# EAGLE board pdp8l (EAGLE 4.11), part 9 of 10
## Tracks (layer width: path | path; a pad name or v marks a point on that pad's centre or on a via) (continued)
OP1  (via drill 0.61) (continued)
  Bottom 0.203: v343,97.38 343.41,96.98 v365.76,96.98 | A09.D1 350.32,263.2 348.69,261.57 344.22,261.57 341.38,258.72 327.15,258.72 325.93,257.5 A11.F1 324.71,257.1 323.09,255.47 317.81,255.47 316.59,254.25 A12.H1 | B13.H2 297.49,183.95 302.77,183.95 B13.H1 | v316.59,205.08 v304.8,205.08
OP1\  (via drill 0.61)
  Route2 0.203: v300.74,146.96 299.52,145.75 299.52,144.93 v294.23,139.65 291.8,137.21 290.98,137.21 C14.A1
  Route15 0.203: v300.74,146.96 301.95,148.18 306.43,143.71 306.43,142.49 319.43,129.49 319.43,128.68 330,118.11 330,116.08 331.22,114.86 C10.J2 | v367.79,125.02 361.29,131.52 356.01,131.52 353.16,134.37 351.94,134.37 348.29,138.02 346.66,138.02 v345.44,139.24
  Bottom 0.203: v367.79,125.02 371.04,125.02 372.26,123.8 C07.E2 | v345.44,139.24 345.03,138.84 339.34,138.84 338.94,139.24 338.94,140.06 313.33,140.06 312.12,138.84 305.61,138.84 304.39,140.06 294.64,140.06 v294.23,139.65
OP2  (via drill 0.61)
  Top 0.203: v345.85,57.96 345.85,52.68 344.63,51.46 D09.F2 | v311.3,126.24 v311.3,115.27 | v302.36,139.24 302.77,139.65 302.77,147.37 301.55,148.59 301.55,200.61 301.14,201.02 301.14,206.3 301.55,206.7 301.55,220.52 298.3,223.77 298.3,233.12 297.08,234.34 A13.P2 | v354.79,70.97 355.19,70.56 355.19,61.62 354.38,60.81 D09.C1 | v365.35,78.69 362.1,81.94 362.1,83.16 363.32,84.38 368.61,84.38 368.61,109.98 369.82,111.2 369.82,113.64 C07.J2
  Route15 0.203: v302.36,139.24 302.36,138.02 301.14,136.8 302.77,135.18 306.83,135.18 308.05,133.96 308.05,133.55 310.9,130.71 310.9,127.05 311.3,126.64 v311.3,126.24
  Bottom 0.203: v345.85,57.96 347.07,59.18 349.91,59.18 350.72,60 353.57,60 D09.C1 | 311.3,115.67 345.85,115.67 346.25,115.27 349.91,115.27 350.32,115.67 368.61,115.67 369.42,114.86 C07.J2 | 311.3,115.67 286.51,115.67 285.29,114.45 281.63,114.45 C14.J2 | v311.3,126.24 307.24,126.24 306.83,126.64 C12.D2 | v311.3,115.27 311.3,115.67 | v354.79,70.97 354.79,77.88 360.48,77.88 361.7,79.1 364.95,79.1 v365.35,78.69
OP2\  (via drill 0.61)
  Route2 0.203: v351.94,100.23 351.94,100.63 363.73,112.42 364.13,112.42 370.23,118.52 371.04,117.7 372.26,117.7 C07.H2
  Route15 0.203: C14.B1 288.14,133.15 289.36,133.15 293.83,128.68 294.64,128.68 296.27,127.05 297.89,127.05 308.86,116.08 314.15,116.08 321.87,108.36 323.09,108.36 331.22,100.23 333.25,100.23 334.47,99.01 C10.P2
  Bottom 0.203: v351.94,100.23 337.31,100.23 335.69,98.6 C10.P2
OP_STROBE\  (via drill 0.61)
  Top 0.203: v319.43,222.15 319.43,224.99 A11.T2 | v362.92,178.66 361.7,177.44 361.7,154.28 360.48,153.06 B08.U2
  Route2 0.203: v322.27,156.31 322.27,155.91 315.77,149.4 314.96,149.4 310.9,145.34 310.9,144.93 303.99,138.02 302.77,138.02 295.05,130.3 295.05,126.24 289.76,120.95 288.14,120.95 C14.F1
  Route15 0.203: v322.27,156.31 322.68,156.31 v325.12,153.87 | v319.43,222.15 348.29,193.29 348.29,192.89 354.38,186.79 354.79,186.79 v362.92,178.66
  Bottom 0.203: v325.12,153.87 327.96,151.03 333.25,151.03 334.47,149.81 335.28,149.81 338.12,152.65 338.94,152.65 340.56,151.03 355.6,151.03 356.82,152.25 359.66,152.25 B08.U2
OUT_STOP2\
  Bottom 0.203: D31.N2 65.84,31.55 70.71,31.55 D31.N1
PANEL_LOCK  (via drill 0.61)
  Route2 0.203: v382.83,103.48 382.83,103.89 384.86,105.92 386.89,105.92 387.71,106.73 387.71,108.76 426.72,147.78 427.53,147.78 445.82,166.06 445.82,167.69 B01.N2 | v377.55,103.48 375.92,103.48 364.54,92.1 v364.54,91.69 | v323.09,90.47 322.68,90.47 313.33,81.13 309.68,81.13 299.11,70.56 298.3,70.56 297.89,70.16 278.38,70.16 v260.1,51.87
  Route15 0.203: v260.1,51.87 258.06,51.87 247.5,62.43 245.87,62.43 170.28,138.02 167.44,138.02 136.14,169.32 136.14,175.41 128.42,183.13 128.42,185.57 107.29,206.7 107.29,207.11 105.26,209.14 105.26,219.71 102.82,222.15 102.82,224.99 A28A.T2
  Bottom 0.203: v377.55,103.48 v382.83,103.48 | v364.54,91.69 363.73,90.88 359.26,90.88 357.63,92.51 356.41,92.51 354.79,90.88 350.72,90.88 348.29,93.32 326.75,93.32 323.9,90.47 v323.09,90.47
PAUSE  (via drill 0.61)
  Top 0.203: v416.15,101.04 416.15,105.51 414.53,107.14 C04.L1
  Route2 0.203: v430.38,77.47 430.38,77.06 426.31,73 426.31,72.19 391.36,37.24 390.14,37.24 364.13,11.23 352.75,11.23 352.35,10.82 349.5,10.82 v343.41,4.72
  Route15 0.203: v416.15,101.04 416.15,95.35 428.35,83.16 428.35,79.5 v430.38,77.47 | v343.41,4.72 324.31,4.72 321.06,1.47 300.33,1.47 297.49,4.32 294.23,4.32 287.73,10.82 286.51,10.82 272.69,24.64 271.07,24.64 269.04,26.67 258.88,26.67 258.06,27.48 255.63,27.48 253.19,29.92 241.4,29.92 234.49,36.83 227.99,36.83 209.3,55.52 204.01,55.52 191.82,67.72 191.01,67.72 v126.39,132.33
  Bottom 0.203: v126.39,132.33 123.55,135.18 114.61,135.18 113.39,136.4 C28.A1
PAUSE\  (via drill 0.61)
  Top 0.203: v421.44,65.28 421.84,65.68 v421.84,103.89
  Bottom 0.203: v421.44,65.28 420.62,65.28 419.81,64.47 415.34,64.47 414.93,64.06 D04.B1 | v421.84,103.89 421.44,104.29 418.19,104.29 C04.M1
PC_ENABLE  (via drill 0.61)
  Top 0.203: v357.23,205.08 357.23,218.49 A08.V2 | v373.48,185.98 374.29,185.17 374.29,160.78 373.07,159.56 AB07.BS2
  Route15 0.203: v357.23,205.08 357.23,202.23 v373.48,185.98
  Bottom 0.203: AB07.BS2 373.48,159.16 374.29,159.97 384.45,159.97 385.27,159.16 AB06.BS2 386.49,159.16 387.3,159.97 397.05,159.97 | 397.05,159.97 397.87,159.16 AB05.BS2 | 409.65,159.97 410.46,159.16 AB04.BS2 | 397.05,159.97 409.65,159.97 | 421.84,159.97 423.06,158.75 AB03.BS2 | 409.65,159.97 421.84,159.97 | 421.84,159.97 435.25,159.97 436.07,159.16 AB02.BS2
PC_ENABLE\  (via drill 0.61)
  Top 0.203: v296.67,112.83 295.05,114.45 295.05,144.53 294.64,144.93 294.64,148.18 295.05,148.59 295.05,175.82 295.45,176.22 v295.45,186.79 295.45,187.2 295.45,203.45 v293.01,205.89
  Route2 0.203: v341.78,212.8 354.38,225.4 356.41,225.4 A08.T2 | v332.44,212.39 329.59,209.55 326.75,209.55 305.61,188.42 v303.58,188.42
  Route15 0.203: v293.01,205.89 284.48,214.43 284.48,215.24 281.23,218.49 A14.V2
  Bottom 0.203: v296.67,112.83 301.55,112.83 302.77,111.61 C13.K1 | v295.45,186.79 299.52,186.79 B13.F1 300.74,187.6 302.77,187.6 v303.58,188.42 | v341.78,212.8 341.38,212.39 v332.44,212.39
PC_LOAD  (via drill 0.61)
  Top 0.203: v358.44,235.56 358.44,231.09 358.04,230.68 358.04,227.43 358.44,227.03 358.44,218.08 358.04,217.68 358.04,203.45 358.44,203.05 358.44,186.79 358.04,186.38 358.04,181.91 357.63,181.51 B08.J2
  Route2 0.203: C14.H1 290.98,118.11 290.98,120.14 305.61,134.77 309.68,134.77 320.24,145.34 321.06,145.34 322.27,146.56 322.27,148.18 347.07,172.97 347.88,172.97 349.1,174.19 349.1,175.01 353.16,179.07 354.79,179.07 356.41,180.7 B08.J2
  Route15 0.203: C14.J1 288.14,114.45 290.58,116.89 C14.H1
  Bottom 0.203: v358.44,235.56 359.66,236.78 368.61,236.78 | 368.61,236.78 369.42,237.59 AB07.AN2 | 381.2,236.78 382.02,237.59 AB06.AN2 | 368.61,236.78 381.2,236.78 | 381.2,236.78 389.74,236.78 390.14,237.19 393.8,237.19 394.61,238 AB05.AN2 395.83,237.59 400.3,237.59 401.12,236.78 402.34,236.78 402.74,237.19 406.4,237.19 407.21,238 AB04.AN2 408.43,238 412.5,238 413.71,236.78 419.4,236.78 420.22,237.59 AB03.AN2 421.44,238 424.28,238 425.5,236.78 432,236.78 432.82,237.59 AB02.AN2
POWER_CLEAR\  (via drill 0.61)
  Top 0.203: v403.15,93.73 403.56,94.13 403.56,102.26 404.37,103.07 404.37,104.29 C05.M1 405.18,105.51 v405.18,106.73 | v262.13,42.11 263.35,43.33 263.35,64.87 264.57,66.09 D16.A1 | v119.48,206.3 120.29,207.11 120.29,226.62 119.08,227.84 A27.S2
  Route2 0.203: v262.13,42.11 261.72,41.71 259.28,41.71 D16.K2 | v372.67,94.13 371.45,94.13 365.35,88.04 365.35,86.41 351.54,72.59 351.54,72.19 349.91,70.56 349.1,70.56 348.69,70.16 347.88,70.16 325.12,47.4 324.31,47.4 v316.18,39.27
  Route15 0.203: v119.48,206.3 119.48,204.67 130.05,194.11 130.05,189.23 153.21,166.06 153.21,164.44 155.25,162.41 155.25,158.75 166.22,147.78 167.03,147.78 242.21,72.59 242.21,72.19 243.84,70.56 244.65,70.56 245.06,70.16 245.87,70.16 v248.31,67.72
  Bottom 0.203: v403.15,93.73 390.96,93.73 389.74,94.94 C06.R1 388.52,94.54 387.71,93.73 373.07,93.73 v372.67,94.13 | v405.18,106.73 419.4,106.73 420.22,107.54 CD03.AL2 | v248.31,67.72 248.72,68.12 261.31,68.12 262.53,66.9 264.57,66.9 D16.A1 | v316.18,39.27 315.77,39.68 264.16,39.68 262.13,41.71 v262.13,42.11
POWER_OK\  (via drill 0.61)
  Top 0.203: v114.61,229.87 114.61,249.38 115.42,250.19 A27.J2
  Route15 0.203: v114.61,229.87 115.01,229.87 151.59,193.29 151.59,192.48 168.25,175.82 168.25,175.01 193.45,149.81 193.45,146.96 218.64,121.77 220.68,121.77 251.56,90.88 263.75,90.88 289.36,65.28 293.83,65.28 322.27,36.83 323.09,36.83 v323.9,37.64
  Bottom 0.203: v323.9,37.64 324.71,36.83 349.5,36.83 350.32,37.64 D09.L1
PROTECT\  (via drill 0.61)
  Top 0.203: v356.41,234.34 356.82,234.75 356.82,237.59 A08.N2 | 320.24,106.32 320.24,90.47 319.43,89.66 C11.T2 319.43,88.44 319.84,88.04 319.84,83.97 321.46,82.35 321.46,79.91 321.87,79.5 v321.87,72.19 | 320.24,106.32 319.43,107.14 C11.L2 | 384.45,3.5 349.5,3.5 349.5,17.73 345.85,21.39 345.85,30.33 | 384.45,3.5 404.77,3.5 413.71,12.45 D04.V1 | 345.85,30.33 345.03,31.14 D09.N2 | 384.45,3.5 384.45,82.75 382.83,84.38 382.83,88.44 C06.T2 | v345.03,48.21 345.85,47.4 345.85,30.33 | v325.53,146.56 325.93,146.15 v325.93,136.4 | v318.62,128.68 320.24,128.68 320.24,106.32
  Route2 0.203: v356.41,234.34 322.68,200.61 321.46,200.61 321.06,200.2 321.06,199.8 308.05,186.79 308.05,185.98 299.52,177.44 299.52,177.04 297.08,174.6 297.08,172.16 B13.M2 | v325.93,136.4 325.93,135.99 v318.62,128.68
  Route15 0.203: C12.R1 312.93,94.54 312.93,92.91 314.96,90.88 316.99,90.88 318.62,89.26 C11.T2 | v321.87,72.19 325.12,68.94 325.12,68.12 v345.03,48.21 | v325.53,146.56 325.12,146.56 310.49,161.19 310.08,161.19 305.21,166.06 304.39,166.06 299.52,170.94 297.49,170.94 B13.M2
PWR  (via drill 0.61)
  Top 0.203: v65.02,90.47 66.24,91.69 66.24,115.27 63.4,118.11 63.4,142.09 v62.99,142.49
  Route2 0.203: v62.99,142.49 62.99,144.93 76,157.94 76,159.56 77.62,161.19 AB30.BR2
  Bottom 0.203: v65.02,90.47 58.12,90.47 55.27,87.63 32.51,87.63 30.89,86 C34.U2
PWR_LOW\  (via drill 0.61)
  Top 0.203: v99.16,96.98 95.1,101.04 95.1,112.01 92.25,114.86 92.25,138.02 95.5,141.28 95.5,163.22 96.32,164.03 v96.32,166.06
  Route15 0.203: v96.32,166.06 66.65,195.73 65.43,195.73 47.55,213.61 47.14,213.61 40.23,220.52 34.95,220.52 v23.16,232.31
  Bottom 0.203: 18.69,236.78 37.8,236.78 39.01,238 A33.N2 | 18.69,236.78 2.03,236.78 2.03,232.31 A36.R2 | v99.16,96.98 117.04,96.98 120.7,93.32 130.45,93.32 131.27,92.51 C26.S2 | v23.16,232.31 18.69,236.78
PWR_SKP\  (via drill 0.61)
  Top 0.203: v45.52,241.66 48.77,244.91 48.77,246.94 A33.K1
  Bottom 0.203: v45.52,241.66 43.89,240.03 17.07,240.03 14.63,242.47 3.66,242.47 2.03,244.09 A36.L2
RD_HOLE1  (via drill 0.61)
  Top 0.203: v12.19,144.12 11.79,144.53 11.79,149.81 9.75,151.84 v9.75,185.98
  Route2 0.203: v9.75,185.98 9.75,192.07 24.79,207.11 24.79,208.33 76,259.54 76,261.16 77.62,262.79 AB30.AD2
  Bottom 0.203: v12.19,144.12 3.25,144.12 3.25,129.49 4.06,128.68 25.2,128.68 26.42,127.46 C34.D2
RD_HOLE2  (via drill 0.61)
  Top 0.203: v83.72,240.84 85.34,242.47 85.34,260.76 84.53,261.57 84.53,262.79 AB30.AD1
  Route2 0.203: v4.06,146.15 5.69,147.78 5.69,150.22 8.13,152.65 8.13,153.87 9.35,155.09 9.35,159.97 40.23,190.86 40.64,190.86 41.05,191.26 41.05,198.98 47.95,205.89 47.95,206.7 56.49,215.24 57.3,215.24 57.71,215.65 58.52,215.65 v83.72,240.84
  Bottom 0.203: v4.06,146.15 2.85,146.15 2.85,129.08 3.66,128.27 21.54,128.27 25.2,124.61 29.26,124.61 29.67,124.21 C34.E2
RD_HOLE3  (via drill 0.61)
  Top 0.203: v82.91,206.3 82.91,227.84 85.75,230.68 85.75,264.01 84.94,264.82 81.28,264.82 81.28,261.16 AB30.AE2
  Route2 0.203: v82.91,206.3 82.09,205.49 82.09,202.23 69.9,190.04 69.9,182.73 69.49,182.32 69.49,177.04 62.18,169.72 62.18,167.28 50.39,155.5 50.39,151.44 49.99,151.03 49.99,148.59 37.8,136.4 37.8,135.59 27.23,125.02 27.23,121.36 C34.F2
RD_HOLE4  (via drill 0.61)
  Top 0.203: v102.41,201.42 98.75,201.42 98.75,227.84 95.5,231.09 95.5,250.19 87.38,258.32 87.38,259.54 AB30.AE1
  Route2 0.203: v52.02,129.08 52.02,129.9 57.3,135.18 57.3,137.21 57.71,137.62 57.71,138.43 61.77,142.49 61.77,148.18 80.06,166.47 80.06,167.69 82.5,170.13 82.5,177.44 88.59,183.54 88.59,187.6 v102.41,201.42
  Bottom 0.203: v52.02,129.08 51.61,128.68 38.61,128.68 32.51,122.58 13.01,122.58 13.01,119.74 16.66,116.08 18.29,116.08 21.13,118.92 28.85,118.92 29.67,118.11 C34.H2
RD_HOLE5  (via drill 0.61)
  Route2 0.203: v5.69,141.28 5.69,146.96 6.1,147.37 6.1,149.81 8.53,152.25 8.53,153.47 9.75,154.69 9.75,159.56 40.64,190.45 41.05,190.45 41.45,190.86 41.45,197.36 45.52,201.42 51.61,201.42 54.86,204.67 58.52,204.67 62.99,209.14 62.99,218.9 84.53,240.44 84.53,241.66 77.62,248.56 79.25,250.19 79.25,252.22 80.47,253.44 AB30.AH2
  Route15 0.203: v5.69,141.28 8.94,138.02 8.94,135.18 26.42,117.7 26.42,114.86 C34.J2
RD_HOLE6  (via drill 0.61)
  Route2 0.203: v4.06,115.67 1.22,118.52 2.85,120.14 2.85,133.96 4.06,135.18 5.28,135.18 6.1,135.99 6.1,136.8 13.01,143.71 13.01,145.75 15.44,148.18 15.44,153.06 19.1,156.72 19.1,157.53 39.01,177.44 39.01,178.26 41.05,180.29 41.05,184.35 45.52,188.82 45.52,190.45 63.4,208.33 63.4,215.24 85.34,237.19 85.34,251.82 86.97,253.44 AB30.AH1
  Bottom 0.203: v4.06,115.67 6.91,112.83 8.13,112.83 8.53,112.42 28.85,112.42 29.67,111.61 C34.K2
RD_HOLE7  (via drill 0.61)
  Top 0.203: v116.23,177.44 117.04,178.26 117.04,211.18 115.42,212.8 115.42,217.68 107.7,225.4 107.7,229.06 103.63,233.12 101.6,233.12 101.6,231.5 100.79,230.68 98.35,230.68 98.35,253.44 86.56,265.23 79.25,265.23 79.25,259.13 78.03,257.91 AB30.AF2
  Route2 0.203: v49.58,109.17 49.99,109.17 76.4,135.59 76.4,138.02 115.82,177.44 v116.23,177.44
  Bottom 0.203: v49.58,109.17 28.45,109.17 27.64,108.36 C34.L2
RD_HOLE8  (via drill 0.61)
  Top 0.203: v31.7,135.99 31.29,135.59 31.29,106.32 30.48,105.51 C34.M2 | v48.36,138.02 48.36,149.81 49.58,151.03 50.39,151.03 50.39,167.69 v48.77,169.32
  Route2 0.203: v57.71,169.72 58.12,169.72 62.18,173.79 62.59,173.79 63.8,175.01 63.8,175.41 68.28,179.88 68.68,179.88 69.09,180.29 69.09,182.73 69.49,183.13 69.49,196.14 101.19,227.84 101.19,242.06 85.34,257.91 84.94,257.5 AB30.AF1
  Bottom 0.203: v31.7,135.99 32.51,135.18 39.42,135.18 42.27,138.02 44.7,138.02 45.11,137.62 47.95,137.62 v48.36,138.02 | v48.77,169.32 49.17,169.72 v57.71,169.72
RDR_FEED_SW  (via drill 0.61)
  Top 0.203: v87.38,133.96 88.19,134.77 88.19,135.59 92.25,139.65 92.25,163.22 93.47,164.44 AB29.BP2
  Route2 0.203: v87.38,133.96 81.69,128.27 77.22,128.27 69.49,120.55 69.49,116.48 40.23,87.22 35.76,87.22 31.29,82.75 27.64,82.75 C34.V2
  Bottom 0.203: AB30.BM1 87.78,170.94 88.19,170.54 91.44,170.54 94.69,167.28 94.69,165.66 93.88,165.66 AB29.BP2
RDR_INT\  (via drill 0.61)
  Top 0.203: v80.47,180.29 81.28,181.1 81.28,182.32 82.09,183.13 82.09,248.56 81.69,248.97 78.44,248.97 78.44,244.91 AB30.AL2
  Route2 0.203: v80.47,180.29 69.49,169.32 69.49,164.44 68.28,163.22 68.28,159.56 AB31.BS2
  Bottom 0.203: A33.L2 40.23,244.09 41.05,243.28 76.4,243.28 77.22,244.09 AB30.AL2
RDR_SKP\  (via drill 0.61)
  Top 0.203: v77.22,170.13 79.25,172.16 79.25,220.12 78.84,220.52 78.84,224.59 79.65,225.4 79.65,245.72 80.87,246.94 AB30.AK2
  Bottom 0.203: A33.H1 49.99,253.85 51.21,252.63 84.53,252.63 85.34,251.82 85.34,248.16 81.28,248.16 AB30.AK2 | v77.22,170.13 67.46,170.13 65.84,168.5 AB31.BN2
READ  (via drill 0.61)
  Top 0.203: v250.34,40.08 248.31,42.11 248.31,43.33 247.9,43.74 247.9,66.09 250.34,68.53 250.34,79.5 244.25,85.6 244.25,93.32 243.03,94.54 C17.R2 | D25.L1 147.52,38.86 146.3,40.08 146.3,55.12 147.52,56.34 D25.D1 147.52,57.96 146.3,59.18 146.3,69.34 149.15,72.19 149.15,83.16 143.05,89.26 143.05,106.73 | 143.05,106.73 143.05,124.61 141.43,126.24 C25.D2 | 143.05,106.73 144.27,105.51 C25.M2
  Route2 0.203: C17.R2 242.21,94.94 238.15,94.94 227.58,84.38 191.82,84.38 149.56,42.11 149.56,40.49 147.93,38.86 D25.L1
  Bottom 0.203: v250.34,40.08 259.69,40.08 261.31,38.46 D16.L1
READER_RUN  (via drill 0.61)
  Top 0.203: v53.24,86.82 53.65,86.41 53.65,78.28 47.95,72.59 47.95,35.2 43.48,35.2 D33.M2
  Bottom 0.203: v53.24,86.82 54.05,86 54.86,86 C32.U2
RESTART\  (via drill 0.61)
  Top 0.203: 409.25,87.22 v407.62,87.22 | 409.25,87.22 409.25,93.32 v409.65,93.73 | v408.03,42.52 409.25,43.74 409.25,87.22 | v311.3,79.5 v311.3,111.2 | v11.79,218.49 11.79,221.34 11.38,221.74 A36.U1 | v134.11,198.58 133.71,198.17 133.71,92.1 136.14,89.66 136.14,86.41 135.74,86 132.49,86 C26.U2 | v392.99,73 392.99,77.06 393.39,77.47 393.39,87.22 394.61,88.44 C05.T2
  Route2 0.203: C02.B1 440.13,132.74 440.13,128.68 442.98,125.83 441.76,124.61 441.76,118.52 422.66,99.42 422.66,97.38 421.03,95.76 CD03.AR2 | v106.48,205.49 127.2,205.49 v134.11,198.58
  Route15 0.203: v408.03,42.52 412.09,38.46 413.71,38.46 D04.L1 | v371.04,70.56 368.2,67.72 367.79,68.12 345.44,68.12 v335.28,78.28
  Bottom 0.203: v407.62,87.22 407.21,87.63 401.12,87.63 400.71,88.04 396.24,88.04 395.83,88.44 C05.T2 | v409.65,93.73 417.78,93.73 419,94.94 420.22,94.94 CD03.AR2 | v311.3,111.2 315.37,111.2 C12.K1 | C26.U2 132.08,85.19 132.08,80.72 199.14,80.72 200.35,81.94 203.2,81.94 206.04,79.1 272.69,79.1 273.1,78.69 295.45,78.69 296.67,79.91 310.9,79.91 v311.3,79.5 311.71,79.5 313.33,79.5 314.15,78.69 314.96,78.69 316.59,77.06 334.06,77.06 v335.28,78.28 | v11.79,218.49 21.13,209.14 38.61,209.14 41.05,206.7 45.52,206.7 45.92,207.11 55.68,207.11 57.3,205.49 v106.48,205.49 | v392.99,73 391.36,71.37 371.86,71.37 v371.04,70.56
RIGHT_SHIFT  (via drill 0.61)
  Top 0.203: v350.32,192.07 350.72,191.67 350.72,189.64 352.75,187.6 352.75,175.41 355.19,172.97 355.19,160.78 353.97,159.56 B09.S1 | v373.07,214.43 374.7,216.05 374.7,264.01 378.76,268.07 382.02,268.07 382.02,264.01 AB06.AD2
  Route2 0.203: v373.07,214.43 366.17,207.52 365.76,207.52 361.7,203.45 361.7,202.64 351.13,192.07 350.72,192.07 v350.32,192.07
  Bottom 0.203: v350.32,192.07 349.1,192.07 348.29,192.89 347.47,192.89 347.07,192.48 340.16,192.48 338.94,193.7 B10.D1 | AB02.AD2 432.82,264.01 428.75,264.01 427.94,264.82 422.66,264.82 421.44,263.6 AB03.AD2 420.22,264.01 419.4,264.82 412.9,264.82 412.09,264.01 408.43,264.01 AB04.AD2 407.21,263.6 406.81,264.01 403.15,264.01 402.34,264.82 393.8,264.82 | 381.2,264.82 375.51,264.82 374.7,264.01 371.04,264.01 370.64,263.6 AB07.AD2 | 381.2,264.82 382.02,264.01 AB06.AD2 | 393.8,264.82 394.61,264.01 AB05.AD2 | 381.2,264.82 393.8,264.82
RUN  (via drill 0.61)
  Top 0.203: v396.65,68.12 392.18,72.59 392.18,85.19 C06.U1 | v416.15,68.12 416.15,64.87 416.97,64.06 416.97,60.81 D04.C1
  Bottom 0.203: v396.65,68.12 397.05,68.53 415.75,68.53 v416.15,68.12
RUN\  (via drill 0.61)
  Top 0.203: v422.66,90.88 422.66,96.98 423.47,97.79 CD03.AP2 | v320.65,19.36 326.75,13.26 326.75,10.82 336.5,10.82 v336.5,12.04
  Route2 0.203: v336.5,12.04 338.53,10.01 339.34,10.82 345.03,10.82 360.48,26.26 361.7,26.26 387.71,52.27 387.71,53.09 405.99,71.37 406.81,71.37 407.62,72.19 407.62,73.81 410.46,76.66 410.46,77.06 411.28,77.88 411.28,78.69 412.09,79.5 413.31,79.5 421.84,88.04 421.84,89.66 422.66,90.47 v422.66,90.88
  Route15 0.203: v222.3,22.2 222.3,22.61 118.26,126.64 116.64,126.64 C27.D2
  Bottom 0.203: v422.66,90.88 397.46,90.88 397.05,91.29 392.99,91.29 392.58,91.69 C06.S1 | v222.3,22.2 223.52,20.98 319.02,20.98 v320.65,19.36
RXD
  Top 0.203: D32.M2 54.86,34.8 50.39,34.8 50.39,33.98 49.99,33.58 41.45,33.58 41.45,52.68 42.27,53.49 D33.E2
SET_IO_ON\  (via drill 0.61)
  Top 0.203: v364.54,139.24 364.54,143.71 364.95,144.12 364.95,179.48 362.92,179.48 362.1,180.29 362.1,182.32 360.88,183.54 B08.H2 | v392.99,139.24 393.39,138.84 393.39,112.42 | 393.39,112.42 392.58,111.61 C06.K1 | v392.99,101.45 393.39,101.85 393.39,112.42
  Route2 0.203: v392.99,101.45 394.61,101.45 C05.N2
  Bottom 0.203: v364.54,139.24 364.95,139.65 392.58,139.65 v392.99,139.24
SHIFT  (via drill 0.61)
  Top 0.203: v86.16,223.37 85.75,222.96 85.75,182.73 84.53,181.51 AB30.BJ1
  Bottom 0.203: v86.16,223.37 89.81,227.03 91.85,227.03 93.07,228.24 AB29.AS2
SHIFT\
  Top 0.203: AB30.BD1 84.53,194.11 85.34,194.92 85.34,225.4 85.75,225.81 89.81,225.81 AB29.AT2
SHUT_DOWN\
  Route2 0.203: A36.U2 4.88,222.96 4.88,224.99 41.45,261.57 47.55,261.57 57.71,271.73 65.02,271.73 67.87,274.57 68.68,274.57 69.49,275.39 71.93,275.39 73.97,277.42 97.54,277.42 116.64,258.32 116.23,257.91 A27.F2
SKIP  (via drill 0.61)
  Top 0.203: v347.88,192.07 349.1,192.07 349.1,181.51 346.25,178.66 v346.25,167.69
  Route2 0.203: v303.58,237.19 306.43,240.03 310.08,240.03 312.52,242.47 312.52,243.69 A12.L1 | v346.25,167.69 346.25,167.28 337.72,158.75 336.91,158.75 332.44,154.28 330.81,154.28 329.18,152.65 B11.U1
  Route15 0.203: v303.58,237.19 304.8,237.19 310.08,231.9 310.08,231.09 312.12,229.06 312.12,228.24 321.46,218.9 321.87,218.9 339.34,201.42 339.34,200.61 v347.88,192.07
SKIP\  (via drill 0.61)
  Top 0.203: v316.18,95.76 317.81,97.38 v317.81,122.99 | v327.96,133.96 327.56,134.37 327.56,135.59 327.15,135.99 327.15,148.59 326.75,149 326.75,156.31 328.37,157.94 B11.S1
  Route2 0.203: v316.18,95.76 304.8,84.38 306.02,83.16 C12.V2 | v317.81,122.99 327.56,132.74 327.56,133.55 v327.96,133.96
SLICE  (via drill 0.61)
  Top 0.203: v194.26,216.86 205.64,228.24 207.26,228.24 A20.S2 | v228.4,230.28 v228.4,159.56
  Bottom 0.203: 218.64,157.53 209.3,157.53 208.48,158.34 B20.S2 | 218.64,157.53 219.86,158.75 B19.S2 | 228.4,157.53 218.64,157.53 | 228.4,157.53 232.05,157.53 232.87,158.34 B18.S2 | v194.26,216.86 155.25,216.86 154.84,217.27 109.32,217.27 108.51,218.08 104.04,218.08 103.63,218.49 A28A.V2 | 218.64,229.87 219.86,228.65 A19.S2 | 218.64,229.87 209.3,229.87 208.48,229.06 A20.S2 | 232.05,229.87 232.87,229.06 A18.S2 | 218.64,229.87 228.4,229.87 | 228.4,229.87 232.05,229.87 | 232.05,229.87 244.65,229.87 245.47,229.06 A17.S2 | v228.4,159.56 228.4,157.53 | 228.4,229.87 v228.4,230.28
SPECIAL_CYCLE\  (via drill 0.61)
  Top 0.203: v291.8,88.85 291.8,85.19 290.98,84.38 290.98,79.1 291.8,78.28 291.8,59.59 293.42,57.96 D13.D2 | v319.02,117.7 319.02,120.14 C11.F2
  Route2 0.203: v291.8,88.85 295.05,92.1 295.05,92.91 301.95,99.82 301.95,101.45 302.36,101.85 303.17,101.85 v319.02,117.7 | C11.A1 328.78,135.99 328.78,133.15 320.24,124.61 320.24,122.17 319.43,121.36 C11.F2
SPIKE_DETECT
  Top 0.203: C32.R1 58.12,95.76 56.9,96.98 56.9,103.48 56.08,104.29 C32.M2
SR00  (via drill 0.61)
  Route2 0.203: v384.05,190.86 388.11,194.92 392.18,194.92 395.43,198.17 396.65,198.17 401.93,203.45 401.93,207.11 410.06,215.24 410.06,216.86 445.41,252.22 447.45,252.22 448.67,253.44 A01.H2
  Bottom 0.203: v384.05,190.86 379.98,190.86 AB07.BE1
SR01  (via drill 0.61)
  Route2 0.203: v445.82,265.23 443.79,263.2 441.76,263.2 430.78,252.22 426.31,252.22 412.9,238.81 412.9,236.78 412.5,236.37 410.46,236.37 409.65,235.56 409.65,233.93 408.84,233.12 407.21,233.12 390.14,216.05 390.14,212.8 388.11,210.77 387.3,210.77 380.8,204.27 380.8,202.64 371.86,193.7 370.64,193.7 AB07.BD2
  Bottom 0.203: v445.82,265.23 444.6,264.01 444.6,257.91 445.82,257.91 A01.F2
SR02  (via drill 0.61)
  Top 0.203: v409.65,191.67 409.65,214.83 410.87,216.05 v410.87,218.9
  Route2 0.203: v410.87,218.9 444.6,252.63 444.6,253.85 447.45,256.69 447.45,257.91 449.07,259.54 A01.E2
  Bottom 0.203: v409.65,191.67 393.39,191.67 392.58,190.86 AB06.BE1
SR03
  Route2 0.203: AB06.BD2 383.24,194.11 383.24,196.14 387.3,200.2 387.3,208.33 390.14,211.18 390.14,211.58 392.18,213.61 392.58,213.61 396.24,217.27 397.46,217.27 441.76,261.57 443.79,261.57 445.41,263.2 A01.D2
SR04  (via drill 0.61)
  Top 0.203: v405.99,205.89 405.99,192.07 405.18,191.26 AB05.BE1 | v445.82,216.86 451.1,222.15 451.1,261.57 452.32,262.79 A01.D1
  Bottom 0.203: v405.99,205.89 406.81,206.7 435.66,206.7 v445.82,216.86
SR05  (via drill 0.61)
  Top 0.203: v426.31,112.01 425.5,112.83 425.5,159.97 v424.28,161.19
  Route15 0.203: v424.28,161.19 424.28,162 397.05,189.23 397.05,191.26 395.43,192.89 AB05.BD2
  Bottom 0.203: v426.31,112.01 431.6,106.73 444.6,106.73 445.41,107.54 C01.L2
SR06  (via drill 0.61)
  Route2 0.203: v434.04,190.86 450.7,174.19 450.7,151.84 448.26,149.4 448.26,141.68 450.7,139.24 450.7,116.89 449.88,116.08 449.88,111.61 C01.K2
  Bottom 0.203: v434.04,190.86 429.97,194.92 420.22,194.92 417.78,192.48 417.78,191.26 AB04.BE1
SR07  (via drill 0.61)
  Top 0.203: v409.65,149 409.65,190.45 408.03,192.07 408.03,192.89 AB04.BD2
  Route15 0.203: v409.65,149 409.65,148.59 443.79,114.45 445.41,114.45 C01.J2
SR08
  Route15 0.203: AB03.BE1 430.78,190.04 430.78,185.57 431.6,184.76 431.6,172.97 442.98,161.59 442.98,160.38 444.19,159.16 444.19,153.06 447.45,149.81 447.45,127.86 450.7,124.61 450.7,119.33 449.48,118.11 C01.H2
SR09  (via drill 0.61)
  Top 0.203: v424.28,139.65 423.47,140.46 423.47,150.62 422.66,151.44 422.66,188.01 v423.06,188.42
  Bottom 0.203: v424.28,139.65 450.7,139.65 450.7,129.49 449.88,128.68 449.48,128.68 449.48,124.61 C01.E2 | v423.06,188.42 423.06,189.64 421.03,191.67 421.03,192.89 AB03.BD2
SR10  (via drill 0.61)
  Top 0.203: v447.45,182.73 447.45,126.24 447.04,125.83 447.04,122.17 446.23,121.36 C01.F2
  Bottom 0.203: v447.45,182.73 447.45,190.04 443.38,190.04 AB02.BE1
SR11  (via drill 0.61)
  Top 0.203: v434.04,130.71 432,132.74 432,191.67 433.22,192.89 AB02.BD2
  Route2 0.203: v402.74,77.47 402.34,77.88 405.59,81.13 405.59,83.57 417.78,95.76 417.78,96.57 434.85,113.64 434.85,115.27 433.63,116.48 431.6,114.45 430.78,114.45 427.94,117.3 433.22,122.58 433.22,124.61 434.85,126.24 434.85,129.9 v434.04,130.71
  Route15 0.203: v402.74,77.47 405.99,74.22 405.99,72.19 409.65,68.53 409.65,66.09 412.09,63.65 412.09,62.03 435.66,38.46 437.29,38.46 439.32,36.42 443.38,36.42 444.6,35.2 448.67,35.2 D01.M2
SR_ENABLE  (via drill 0.61)
  Top 0.203: v369.82,220.93 368.61,222.15 368.61,254.25 366.98,255.88 366.98,259.54 A08.E1
  Route15 0.203: v369.82,220.93 370.23,220.93 371.04,220.12 371.04,218.49 375.92,213.61 377.55,213.61 390.14,201.02 390.14,198.98 391.77,197.36 AB06.BC1
  Bottom 0.203: AB02.BC1 442.16,196.54 440.94,195.33 434.44,195.33 433.63,196.14 430.38,196.14 AB03.BC1 429.56,197.36 429.16,197.76 424.69,197.76 424.28,198.17 419.4,198.17 418.19,196.95 AB04.BC1 416.97,197.36 413.71,197.36 412.9,198.17 406.81,198.17 405.59,196.95 AB05.BC1 404.37,197.36 403.56,198.17 393.39,198.17 392.58,197.36 AB06.BC1 391.36,196.95 390.14,198.17 380.8,198.17 379.98,197.36 AB07.BC1
STOP_COMPLETE
  Bottom 0.203: AB30.BN2 77.22,167.69 73.97,167.69 73.15,166.88 73.15,163.22 89,163.22 89.81,162.41 AB29.BR2
STOP_OK  (via drill 0.61)
  Top 0.203: v119.48,211.99 119.08,212.39 119.08,220.12 117.86,221.34 117.86,252.63 118.67,253.44 A27.H2
  Route2 0.203: v23.57,251.82 7.32,235.56 5.28,235.56 A36.P2
  Route15 0.203: v325.12,42.52 323.49,42.52 316.99,49.02 311.71,49.02 290.17,70.56 288.95,70.56 v278.38,81.13 | v245.06,89.66 233.68,101.04 232.87,101.04 195.88,138.02 193.45,138.02 v119.48,211.99
  Bottom 0.203: v23.57,251.82 27.64,255.88 116.64,255.88 118.26,254.25 A27.H2 | v325.12,42.52 352.75,42.52 353.57,41.71 D09.K1 | v278.38,81.13 271.88,81.13 265.38,87.63 258.88,87.63 256.44,90.07 245.47,90.07 v245.06,89.66
STROBE\  (via drill 0.61)
  Top 0.203: v422.66,83.57 422.66,55.52 423.47,54.71 CD03.BE2 | v241.4,68.53 241.4,83.16 242.62,84.38 242.62,88.44 C17.T2 242.62,89.66 241.4,90.88 241.4,143.71 v241,144.12 | v325.93,69.34 325.53,68.94 325.53,65.68 323.9,64.06 323.9,50.24 324.71,49.43 326.75,49.43 326.75,55.12 325.53,56.34 D11.D1 | v31.29,141.68 31.29,157.12 30.48,157.94 B34.S2
  Route2 0.203: C04.N2 408.43,102.26 408.43,104.29 417.37,113.23 417.37,115.27 425.09,122.99 425.09,125.02 415.75,134.37 417.37,135.99 C04.A1
  Route15 0.203: CD03.BE2 424.28,53.49 424.28,50.65 434.04,40.89 434.85,40.89 435.66,40.08 438.51,40.08 439.73,38.86 D02.L1 | v422.66,83.57 422.66,83.97 415.75,90.88 415.75,91.69 409.65,97.79 409.65,99.82 408.43,101.04 C04.N2 | v381.2,53.49 379.58,51.87 v373.07,58.37
  Bottom 0.203: v241.4,68.53 241.81,68.94 288.54,68.94 288.95,68.53 312.52,68.53 313.33,69.34 v325.93,69.34 | v31.29,141.68 32.51,140.46 106.88,140.46 108.1,141.68 113.39,141.68 114.2,142.49 123.55,142.49 123.95,142.09 125.58,142.09 126.8,143.31 127.61,143.31 128.42,142.49 208.08,142.49 208.89,143.31 238.56,143.31 239.37,144.12 v241,144.12 | v381.2,53.49 382.83,53.49 384.45,51.87 387.3,51.87 388.11,52.68 421.84,52.68 423.06,53.9 CD03.BE2 | v373.07,58.37 370.23,55.52 336.5,55.52 336.09,55.12 330.4,55.12 328.78,56.74 325.93,56.74 D11.D1
STROBE_FIELD0  (via drill 0.61)
  Top 0.203: A18.D1 236.12,262.79 235.31,261.98 235.31,233.12 236.12,232.31 A18.R1 236.12,231.09 235.31,230.28 235.31,206.3 235.71,205.89 235.71,201.42 235.31,201.02 235.31,199.39 236.12,198.58 236.12,194.11 B18.D1 236.53,192.89 237.34,192.07 237.34,188.42 237.74,188.01 237.74,171.75 238.15,171.35 238.15,163.63 | A20.R1 211.73,232.31 212.55,233.12 212.55,261.57 211.33,262.79 A20.D1 | B20.D1 211.33,192.89 212.55,191.67 212.55,163.22 211.73,162.41 B20.R1 | 225.15,191.67 223.93,192.89 B19.D1 | 225.15,191.67 225.15,179.88 222.71,177.44 222.71,163.22 223.52,162.41 B19.R1 | 238.15,163.63 236.93,162.41 B18.R1 | v238.15,93.73 238.15,163.63 | 225.15,191.67 225.15,229.87 223.93,231.09 A19.R1
  Bottom 0.203: A18.R1 237.34,231.9 238.56,233.12 247.9,233.12 248.72,232.31 A17.R1 | A18.D1 237.34,263.2 238.15,262.38 245.87,262.38 246.69,263.2 248.72,263.2 A17.D1 | A20.R1 211.73,231.5 212.95,230.28 221.89,230.28 223.11,231.5 A19.R1 | A20.D1 211.73,264.01 212.55,264.82 221.49,264.82 222.71,263.6 223.11,263.6 A19.D1 | 222.3,160.78 212.55,160.78 211.73,161.59 B20.R1 | 222.3,160.78 223.11,161.59 B19.R1 | 222.3,160.78 235.71,160.78 236.12,161.19 B18.R1 | v238.15,93.73 244.25,93.73 245.47,92.51 C17.S2
SYNC  (via drill 0.61)
  Top 0.203: v327.56,126.64 327.15,127.05 327.15,135.18 326.75,135.59 326.75,147.78 325.93,148.59 B11.V1
  Route2 0.203: v327.56,126.64 325.12,124.21 322.68,124.21 C11.E2
TAD  (via drill 0.61)
  Route2 0.203: v327.96,148.18 327.96,147.78 316.99,136.8 316.59,136.8 C12.A1
  Route15 0.203: v347.07,147.37 347.07,146.96 364.13,129.9 364.95,129.9 375.51,119.33 377.14,119.33 378.76,117.7 C07.H1
  Bottom 0.203: v327.96,148.18 328.37,147.78 330.4,147.78 331.22,146.96 346.66,146.96 v347.07,147.37
TAD\  (via drill 0.61)
  Top 0.203: v310.08,101.85 310.08,99.01 C12.P2 | v350.72,122.58 350.72,126.24 C09.D1
  Route2 0.203: v310.08,101.85 310.08,102.26 329.59,121.77 330,121.77 v336.91,128.68
  Bottom 0.203: v336.91,128.68 346.25,128.68 347.47,127.46 350.32,127.46 C09.D1 | v350.72,122.58 373.89,122.58 375.51,120.95 C07.F1
TP1  (via drill 0.61)
  Top 0.203: v386.08,42.93 386.08,46.99 D06.H2 | v442.57,39.68 442.57,35.61 D02.M1 | v301.55,231.09 301.55,257.91 303.17,259.54 A13.E1 | v286.11,214.83 286.11,178.26 286.92,177.44 286.92,176.22 285.7,175.01 v285.7,159.16 | v375.51,48.21 374.29,49.43 374.29,75.03 v373.89,75.44 | v338.53,110.39 336.09,112.83 336.09,146.96 334.87,148.18 v334.87,150.62
  Route2 0.203: v301.55,231.09 301.55,230.68 286.11,215.24 v286.11,214.83
  Route15 0.203: v373.89,75.44 366.57,82.75 366.57,83.57 357.23,92.91 356.82,92.91 350.72,99.01 349.5,99.01 338.53,109.98 v338.53,110.39 | v334.87,150.62 334.47,150.62 v326.34,158.75
  Bottom 0.203: v386.08,42.93 389.33,39.68 v442.57,39.68 | v285.7,159.16 288.54,156.31 293.42,156.31 B13.T2 294.23,155.91 295.05,156.72 301.95,156.72 302.36,156.31 305.21,156.31 306.02,157.12 319.84,157.12 321.46,158.75 B11.S2 322.68,158.75 v326.34,158.75 | v375.51,48.21 377.55,46.18 384.45,46.18 385.27,46.99 D06.H2
TP2  (via drill 0.61)
  Top 0.203: v312.12,53.9 311.3,53.09 311.3,48.21 315.37,48.21 D12.H1 | v285.29,127.05 285.29,67.72 289.36,63.65 v289.36,55.12 | 390.14,52.27 389.33,51.46 D06.F1 | 390.14,52.27 390.14,77.47 389.33,78.28 389.33,80.72 390.14,81.53 v390.14,91.29 | v390.96,33.58 390.14,34.39 390.14,52.27 | v386.49,106.73 386.89,106.32 386.89,92.91 386.49,92.51 C06.S2
  Bottom 0.203: 314.15,55.93 316.18,57.96 317.81,57.96 | 314.15,55.93 v312.12,53.9 | 317.81,57.96 318.21,57.96 318.62,58.37 329.18,58.37 330,57.56 331.22,57.56 D10.D2 | v285.29,127.05 281.63,127.05 C14.D2 | v289.36,55.12 290.17,55.93 314.15,55.93 | v390.14,91.29 389.74,91.69 386.49,91.69 C06.S2 | v390.96,33.58 433.63,33.58 434.44,32.77 438.91,32.77 439.32,32.36 D02.N1 | v386.49,106.73 386.89,106.32 403.15,106.32 404.37,107.54 406.81,107.54 407.21,107.95 C04.L2 | 317.81,57.96 317.81,52.68 332.84,52.68 334.06,51.46 336.91,51.46 338.12,52.68 382.83,52.68 384.05,51.46 388.52,51.46 D06.F1
TP2\  (via drill 0.61)
  Top 0.203: v440.54,60 441.76,58.78 441.76,33.98 442.16,33.58 442.16,29.52 442.57,29.11 D02.P1
  Route2 0.203: v418.59,101.85 418.59,101.45 416.15,99.01 416.15,96.98 414.93,95.76 C04.R1
  Route15 0.203: B08.M2 360.07,171.35 357.63,168.91 B08.N2 357.63,167.69 357.63,166.88 358.44,166.06 358.44,164.85 365.76,157.53 366.57,157.53 367.39,156.72 367.39,155.5 376.73,146.15 376.73,143.71 385.27,135.18 389.33,135.18 403.15,121.36 403.15,119.74 403.56,119.33 403.56,116.48 403.96,116.08 408.43,116.08 415.75,108.76 415.75,104.7 v418.59,101.85 | v440.54,60 428.75,71.78 428.75,78.28 423.47,83.57 423.47,83.97 416.15,91.29 416.15,92.91 414.53,94.54 C04.R1
TP3  (via drill 0.61)
  Top 0.203: 387.71,74.22 387.71,100.23 388.52,101.04 C06.N1 | 387.71,74.22 387.71,45.77 388.52,44.96 D06.J1 | v404.77,119.33 405.99,120.55 405.99,135.18 405.18,135.99 C05.A1 | A13.M1 303.17,242.06 301.95,243.28 301.95,248.16 303.17,249.38 303.17,253.44 A13.H1 303.58,254.66 303.58,258.32 304.39,259.13 304.39,261.16 301.95,263.6 301.95,271.73 302.77,272.54 A13.A1 | C14.E1 290.17,124.61 289.36,125.42 289.36,138.02 290.58,139.24 290.58,150.62 291.8,151.84 291.8,204.27 290.58,205.49 290.58,220.52 291.8,221.74 291.8,226.62 290.58,227.84 A14.S1 | 387.71,74.22 v388.11,74.22
  Route2 0.203: C05.D2 395.83,127.46 395.83,129.49 401.12,134.77 403.15,134.77 404.37,135.99 C05.A1 | v404.77,119.33 390.96,105.51 390.96,103.89 389.33,102.26 C06.N1 | A14.S1 290.98,229.06 293.01,229.06 301.55,237.59 301.55,239.62 302.77,240.84 A13.M1
  Route15 0.203: C14.E1 290.98,123.39 294.23,123.39 300.74,116.89 301.55,116.89 302.36,116.08 303.99,116.08 305.61,114.45 C12.J2 306.83,114.45 310.49,114.45 314.96,109.98 315.37,109.98 319.43,105.92 323.09,105.92 323.49,105.51 323.49,105.1 324.31,104.29 324.31,100.63 340.56,84.38 347.07,84.38 351.54,79.91 353.16,79.91 356.01,77.06 358.44,79.5 365.76,79.5 366.17,79.1 367.39,79.1 373.07,73.41 374.7,75.03 374.7,75.44 v375.92,76.66
  Bottom 0.203: C04.N1 413.71,101.45 412.9,100.63 408.84,100.63 408.43,100.23 390.96,100.23 389.74,101.45 C06.N1 | v388.11,74.22 385.67,76.66 v375.92,76.66
TP4  (via drill 0.61)
  Top 0.203: C08.N1 363.32,101.04 363.32,98.6 361.7,96.98 361.7,93.32 360.88,92.51 C08.S2 360.07,91.29 359.26,90.47 359.26,86.41 358.85,86 v358.85,71.37 | v358.04,103.07 358.04,106.32 357.23,107.14 C08.L2 | v418.59,132.74 419.4,131.93 v419.4,94.13 | D10.S2 335.28,23.01 336.91,24.64 336.91,30.33 337.72,31.14 D10.N1 | 337.72,32.36 336.09,33.98 336.09,37.64 332.44,37.64 D10.L2 | 337.72,32.36 D10.N1 | 337.72,32.36 337.72,35.61 336.91,36.42 336.91,62.03 337.72,62.84 D10.B1 337.72,64.06 337.31,64.47 v337.31,70.56 | 337.72,32.36 D10.N1 | 308.05,70.16 308.05,142.09 309.68,143.71 309.68,151.84 B12.U2 | 308.05,70.16 308.05,49.43 309.27,48.21 D12.H2 | v307.64,70.16 308.05,70.16
  Bottom 0.203: v358.04,103.07 359.26,101.85 362.92,101.85 C08.N1 | 419.4,93.32 440.94,93.32 442.16,92.1 C02.S1 | 419.4,93.32 412.5,93.32 411.68,92.51 C04.S2 410.46,92.51 409.65,92.51 408.84,93.32 404.37,93.32 403.96,92.91 402.74,92.91 402.34,93.32 361.7,93.32 360.88,92.51 C08.S2 | v418.59,132.74 415.34,132.74 414.93,133.15 C04.B1 | 419.4,93.32 v419.4,94.13 | v307.64,70.16 336.91,70.16 v337.31,70.56 337.31,70.97 340.16,70.97 340.97,70.16 357.63,70.16 v358.85,71.37
TS1  (via drill 0.61)
  Top 0.203: v323.49,257.5 323.49,260.76 322.68,261.57 321.06,261.57 321.06,259.13 320.65,258.72 v320.65,246.94
  Route2 0.203: v356.41,213.21 356.41,209.55 353.16,206.3 352.35,206.3 349.1,203.05 349.1,202.64 329.18,182.73 328.78,182.73 328.37,182.32 328.37,181.51 330,179.88 331.22,181.1 B10.J2
  Route15 0.203: v402.34,130.71 400.3,132.74 400.3,143.31 398.68,144.93 395.43,144.93 v360.48,179.88 | v323.49,257.5 321.06,259.94 316.59,259.94 A12.E1 | v320.65,246.94 321.06,246.94 325.53,242.47 325.93,242.47 326.34,242.06 326.34,240.03 331.22,235.15 332.84,235.15 334.47,233.53 338.94,233.53 352.35,220.12 352.35,218.9 354.79,216.46 354.79,214.83 v356.41,213.21
  Bottom 0.203: v402.34,130.71 403.15,131.52 407.62,131.52 413.31,125.83 415.34,125.83 416.97,124.21 C04.E1 | v360.48,179.88 360.07,179.48 333.65,179.48 332.44,180.7 B10.J2
TS1\  (via drill 0.61)
  Route2 0.203: v395.02,99.01 396.65,100.63 396.65,103.48 397.05,103.89 397.05,105.92 399.49,108.36 399.9,108.36 411.68,120.14 413.71,120.14 C04.F1 | v415.34,60 414.93,60 v387.71,32.77
  Route15 0.203: C30.P2 80.47,99.01 80.06,99.01 78.03,101.04 C30.N2 | v395.02,99.01 395.43,99.01 398.27,96.16 398.27,94.54 409.25,83.57 409.25,73 414.12,68.12 414.12,65.28 412.5,63.65 412.5,62.84 v415.34,60 | v179.63,33.98 179.22,33.98 142.24,70.97 141.83,70.97 130.05,82.75 130.05,83.16 v124.77,88.44
  Bottom 0.203: v387.71,32.77 387.3,33.17 341.78,33.17 338.94,30.33 310.08,30.33 307.24,33.17 304.39,33.17 301.55,30.33 269.04,30.33 265.79,27.08 258.47,27.08 258.06,27.48 255.63,27.48 253.19,29.92 221.49,29.92 217.83,33.58 180.03,33.58 v179.63,33.98 | v124.77,88.44 119.48,93.73 88.59,93.73 84.12,98.2 81.69,98.2 C30.P2
TS2  (via drill 0.61)
  Top 0.203: v305.61,235.15 304.8,235.97 304.8,257.1 305.21,257.5 305.21,261.98 306.02,262.79 A12.D2 | v321.46,95.35 321.06,95.76 321.06,109.58 321.87,110.39 C11.K2 | 409.65,27.08 v405.59,27.08 | 409.65,27.08 409.65,17.73 410.87,16.51 D04.U2 | 409.65,27.08 409.65,92.51 410.46,93.32 410.46,97.38 410.87,97.79 C04.P2 | v316.99,79.1 317.4,79.5 317.4,92.51 316.99,92.91 316.99,94.94 318.62,94.94 C11.R2 | v385.27,213.61 384.86,213.21 384.86,204.27 384.45,203.86 384.45,200.2 386.89,197.76 386.89,133.15 384.45,130.71 384.45,128.27 v384.86,127.86
  Route15 0.203: v316.99,79.1 317.81,78.28 317.81,66.9 352.35,32.36 352.35,28.7 350.32,26.67 348.29,28.7 D09.P2 | v385.27,213.61 364.54,234.34 364.13,234.34 341.38,257.1 341.38,259.54 A10.E1 | v384.86,127.86 384.86,127.46 387.3,125.02 388.11,125.02 405.99,107.14 405.99,105.51 409.25,102.26 409.25,101.04 411.28,99.01 C04.P2
  Bottom 0.203: A13.D2 294.23,263.2 295.05,262.38 304.8,262.38 305.61,263.2 A12.D2 306.83,263.2 308.05,261.98 316.99,261.98 319.84,259.13 339.75,259.13 340.56,259.94 A10.E1 | v305.61,235.15 308.86,235.15 A12.P2 | v321.46,95.35 319.84,95.35 C11.R2 | v405.59,27.08 349.5,27.08 348.29,28.3 D09.P2
TS3  (via drill 0.61)
  Top 0.203: 333.65,124.61 332.03,126.24 C10.D2 | 333.65,124.61 333.65,112.42 334.47,111.61 C10.K2 335.28,110.39 335.28,107.54 339.34,103.48 339.34,90.47 339.75,90.07 v339.75,70.16 | 333.65,131.52 333.65,124.61 | 333.65,131.52 333.65,189.23 334.47,190.04 B10.E2 334.87,191.26 334.87,194.11 336.09,195.33 336.09,218.08 v335.69,218.49 | v418.59,70.56 418.59,80.72 419,81.13 419,90.07 417.78,91.29 C04.S1 | 333.65,131.52 v334.06,131.52 | v326.34,227.84 326.34,230.28 325.53,231.09 A11.R1
  Route2 0.203: v302.77,238.81 333.65,269.7 336.5,269.7 336.91,270.1 336.91,270.51 339.34,272.95 340.56,272.95 A10.A1
  Route15 0.203: A12.M1 316.59,240.84 318.62,240.84 323.49,235.97 323.49,233.93 325.12,232.31 A11.R1 | v308.86,133.96 307.24,135.59 304.8,135.59 303.99,136.4 C13.A1 | v335.69,218.49 v326.34,227.84
  Bottom 0.203: v302.77,238.81 303.99,240.03 314.55,240.03 315.37,240.84 A12.M1 | v308.86,133.96 311.71,133.96 312.12,133.55 C12.B1 313.33,133.15 314.15,132.33 318.21,132.33 319.43,131.12 321.06,131.12 321.46,131.52 323.49,131.52 323.9,131.12 326.34,131.12 327.56,132.33 330.81,132.33 331.62,131.52 v334.06,131.52 | v418.59,70.56 417.78,69.75 340.16,69.75 v339.75,70.16
TS3\  (via drill 0.61)
  Top 0.203: v340.16,9.2 317.4,9.2 v317.4,19.36
  Route2 0.203: v408.43,72.59 408.43,71.37 406.81,69.75 405.99,69.75 362.1,25.86 362.1,25.04 360.48,23.42 358.44,23.42 345.44,10.41 341.38,10.41 v340.16,9.2
  Route15 0.203: v404.77,81.53 404.77,78.28 405.59,77.47 405.59,75.44 v408.43,72.59 | v174.75,31.55 174.75,31.95 116.23,90.47 116.23,90.88 110.54,96.57 105.66,96.57 86.16,116.08 82.91,116.08 81.69,117.3 C30.H2
  Bottom 0.203: C30.J2 78.03,114.86 80.06,116.89 80.47,116.89 C30.H2 | v404.77,81.53 407.21,83.97 415.75,83.97 416.97,85.19 C04.U1 | v317.4,19.36 316.18,20.57 199.14,20.57 186.54,33.17 176.38,33.17 v174.75,31.55
TS4  (via drill 0.61)
  Top 0.203: A10.K1 340.97,246.94 340.97,242.06 A10.M1 340.97,240.84 340.16,240.03 340.16,231.9 v339.75,231.5 | 298.7,170.13 298.7,147.78 299.92,146.56 299.92,135.18 298.7,133.96 298.7,124.61 299.92,123.39 299.92,121.36 C13.F1 300.33,120.14 301.95,118.52 v301.95,105.92 301.95,105.51 v301.95,70.97 | 298.7,170.13 298.7,188.01 299.92,189.23 299.92,192.89 B13.D1 | v324.31,48.62 324.31,39.68 325.12,38.86 D11.L1 | v371.86,81.53 370.23,79.91 v370.23,68.12 | 298.7,170.13 v299.11,170.13
  Route2 0.203: v340.56,68.12 340.16,67.72 340.16,63.65 325.12,48.62 324.71,48.62 v324.31,48.62 | v339.75,231.5 324.31,216.05 323.9,216.05 310.9,203.05 310.9,202.64 303.58,195.33 301.95,195.33 300.74,194.11 B13.D1
  Route15 0.203: v301.95,70.97 v324.31,48.62
  Bottom 0.203: v301.95,105.92 301.55,106.32 272.69,106.32 271.88,105.51 C15.M2 | v371.86,81.53 372.26,81.13 376.73,81.13 377.55,81.94 378.36,81.94 379.58,80.72 405.59,80.72 407.21,82.35 C04.V2 | v340.56,68.12 v370.23,68.12 | v299.11,170.13 325.53,170.13 326.34,169.32 330.4,169.32 331.22,168.5 B10.N2
TS4\  (via drill 0.61)
  Top 0.203: v206.45,7.98 182.47,7.98 182.47,4.72 182.07,4.32 117.45,4.32 117.45,28.3 111.35,34.39 111.35,70.16 113.79,72.59 113.79,82.75 110.95,85.6 110.95,128.27 109.73,129.49 109.73,132.74 C28.B1
  Route2 0.203: v363.73,61.62 354.79,52.68 343.81,52.68 305.21,14.07 305.21,13.66 304.8,13.26 302.77,13.26 300.74,11.23 209.7,11.23 v206.45,7.98
  Route15 0.203: v423.47,64.87 423.88,64.47 425.09,65.68 425.09,67.31 423.06,69.34 423.06,74.22 414.93,82.35 C04.V1
  Bottom 0.203: v423.47,64.87 423.47,61.62 422.66,61.62 422.25,61.21 421.03,61.21 419.81,62.43 415.34,62.43 414.93,62.03 406.81,62.03 406.4,62.43 402.74,62.43 402.34,62.03 393.39,62.03 392.99,62.43 389.74,62.43 389.33,62.03 380.8,62.03 380.39,62.43 377.14,62.43 376.73,62.03 368.2,62.03 367.79,62.43 364.54,62.43 v363.73,61.62
TT0\  (via drill 0.61)
  Top 0.203: v24.38,144.12 23.98,144.53 23.98,150.62 25.2,151.84 25.2,168.1 22.35,170.94 22.35,174.19 25.6,177.44 25.6,194.92 28.45,197.76 28.45,214.83 v28.04,215.24
  Route2 0.203: v16.26,215.65 14.63,217.27 15.44,218.08 15.44,222.15 17.07,223.77 21.13,223.77 44.3,246.94 44.3,252.63 59.33,267.67 60.96,267.67 61.37,267.26 A32.C1
  Route15 0.203: v24.38,144.12 28.85,139.65 28.85,135.99 32.11,132.74 32.11,132.33 53.24,111.2 54.86,111.2 C32.K2
  Bottom 0.203: v28.04,215.24 27.64,215.65 v16.26,215.65
TT1\
  Top 0.203: C32.R2 52.02,95.76 51.21,96.57 51.21,204.67 52.43,205.89 52.43,216.05 51.21,217.27 51.21,255.88 52.02,256.69 A32.F2
TT2\  (via drill 0.61)
  Top 0.203: v17.48,131.93 18.69,133.15 18.69,142.09 15.85,144.93 v15.85,174.6 | v56.49,226.62 57.3,227.43 57.3,238.4 56.49,239.22 56.49,240.44 57.3,241.25 57.3,248.97 58.52,250.19 A32.J1
  Route2 0.203: v15.85,174.6 16.26,174.6 34.54,192.89 34.54,196.95 45.11,207.52 45.52,207.52 47.14,209.14 47.14,217.27 v56.49,226.62
  Route15 0.203: v17.48,131.93 17.88,131.93 54.86,94.94 54.86,92.51 C32.S2
TT3\  (via drill 0.61)
  Top 0.203: v92.25,195.73 92.25,167.28 88.59,163.63 88.59,140.46 85.34,137.21 v85.34,115.27
  Route15 0.203: v92.25,195.73 60.15,227.84 60.15,232.31 56.08,236.37 56.08,240.84 A32.M2
  Bottom 0.203: v85.34,115.27 85.34,111.2 82.91,111.2 81.28,109.58 60.55,109.58 59.33,108.36 C32.L1
TT4\
  Top 0.203: C32.M1 61.77,105.51 60.55,106.73 60.55,141.28 63.4,144.12 63.4,233.12 62.18,234.34 A32.P1
TT5\  (via drill 0.61)
  Top 0.203: v93.07,193.29 95.1,191.26 95.1,169.32 91.85,166.06 91.85,142.9 86.16,137.21 v86.16,93.73
  Route15 0.203: v93.07,193.29 v62.59,223.77
  Bottom 0.203: v62.59,223.77 54.05,223.77 52.83,224.99 A32.T2 | v86.16,93.73 62.99,93.73 58.93,97.79 56.08,97.79 C32.P2
TT6\  (via drill 0.61)
  Top 0.203: v105.26,188.01 104.85,187.6 104.85,149 v105.26,148.59
  Route2 0.203: v105.26,148.59 105.26,139.65 56.49,90.88 54.46,90.88 52.83,89.26 C32.T2
  Route15 0.203: v105.26,188.01 60.15,233.12 60.15,238.81 39.42,259.54 45.92,266.04 48.77,266.04 A33.C1
TT7\  (via drill 0.61)
  Top 0.203: v8.94,258.72 9.35,258.32 9.35,222.56 4.06,217.27 4.06,213.21 3.25,212.39 3.25,164.03 5.28,162 v5.28,160.38
  Route15 0.203: v5.28,160.38 6.1,159.56 6.1,144.53 19.91,130.71 21.13,130.71 48.36,103.48 49.99,103.48 51.61,101.85 C32.N2
  Bottom 0.203: v8.94,258.72 37.8,258.72 39.01,257.5 A33.F2
TT_AC_CLEAR\  (via drill 0.61)
  Top 0.203: A33.R1 46.74,231.9 48.77,233.93 48.77,234.34 A33.P1 | v98.35,99.01 102.01,102.67 102.01,123.8 104.44,126.24 104.44,168.91 v102.82,170.54
  Route2 0.203: v98.35,99.01 55.68,56.34 55.68,54.71 D32.E2
  Route15 0.203: v102.82,170.54 86.56,186.79 86.16,186.79 85.34,187.6 85.34,188.01 66.65,206.7 66.24,206.7 65.84,207.11 65.84,211.18 59.74,217.27 58.12,217.27 47.95,227.43 47.95,229.46 46.33,231.09 A33.R1
  Bottom 0.203: A33.N1 46.33,237.59 48.36,235.56 48.77,235.56 A33.P1
TT_INT\  (via drill 0.61)
  Route15 0.203: v255.22,36.02 255.22,36.42 225.55,66.09 225.55,66.5 213.77,78.28 213.36,78.28 143.87,147.78 140.61,147.78 103.23,185.17 101.6,185.17 97.54,189.23 92.66,189.23 47.95,233.93 47.95,234.34 43.48,238.81 43.48,240.84 A33.M2
  Bottom 0.203: v255.22,36.02 257.66,33.58 301.95,33.58 302.77,34.39 D13.M1
TT_SKIP\  (via drill 0.61)
  Top 0.203: v121.51,247.34 123.95,244.91 123.95,206.7 127.2,203.45 127.2,186.79 v129.64,184.35
  Route15 0.203: v129.64,184.35 138.18,175.82 138.18,174.6 142.24,170.54 142.24,169.32 161.75,149.81 161.75,147.37 205.64,103.48 207.26,103.48 229.62,81.13 232.46,81.13 243.43,70.16 244.25,70.16 246.28,68.12 246.69,68.12 247.9,66.9 248.72,66.9 267.41,48.21 268.22,48.21 295.45,20.98 296.27,20.98 299.52,17.73 301.55,17.73 302.77,16.51 D13.U1
  Bottom 0.203: v121.51,247.34 113.39,255.47 41.45,255.47 41.45,253.44 42.27,252.63 44.3,252.63 45.52,251.41 A33.J1
TTI_CLOCK  (via drill 0.61)
  Top 0.203: v58.52,96.98 58.52,101.04 C32.N1
  Bottom 0.203: v58.52,96.98 41.45,96.98 40.23,95.76 C33.R2
TTI_FLAG\  (via drill 0.61)
  Top 0.203: v279.2,255.88 279.6,256.29 279.6,261.57 280.82,262.79 A14.D2
  Route2 0.203: v104.04,123.8 124.36,144.12 125.17,144.12 125.98,144.93 127.61,144.93 167.84,185.17 167.84,204.67 v215.8,252.63
  Bottom 0.203: v104.04,123.8 102.41,122.17 53.65,122.17 52.83,121.36 C32.F2 | v215.8,252.63 242.62,252.63 245.47,255.47 251.16,255.47 251.56,255.88 v279.2,255.88
TTI_SKIP\  (via drill 0.61)
  Top 0.203: v62.59,81.94 62.99,81.53 62.99,72.59 57.3,66.9 57.3,49.43 56.08,48.21 D32.H2
  Route2 0.203: v62.59,81.94 93.07,112.42 97.13,112.42 120.29,135.59 120.29,136.8 168.25,184.76 168.25,203.86 v198.73,234.34
  Bottom 0.203: v198.73,234.34 204.01,239.62 232.46,239.62 232.87,240.03 258.06,240.03 259.28,238.81 260.5,238.81 261.31,239.62 279.2,239.62 280.42,238.4 A14.N2
TTO_CLOCK\  (via drill 0.61)
  Top 0.203: v57.3,113.23 57.3,107.14 60.15,104.29 60.15,98.2 63.4,94.94 63.4,28.7 67.46,28.7 D31.P2
  Bottom 0.203: v57.3,113.23 54.86,115.67 49.58,115.67 45.52,111.61 43.48,111.61 C33.K2
TTO_ENABLE
  Bottom 0.203: C31.K2 68.68,110.79 73.97,110.79 C31.K1
TTO_ENABLE\
  Top 0.203: C31.L1 71.53,108.76 73.15,110.39 73.15,112.42 74.37,113.64 74.37,116.89 C31.H1
TTO_FLAG\  (via drill 0.61)
  Top 0.203: v225.96,220.52 v225.96,210.36
  Route2 0.203: v225.96,210.36 225.55,210.36 173.13,157.94 172.31,157.94 151.99,137.62 151.99,135.59 123.95,107.54 123.95,106.73 98.35,81.13 98.35,72.19 95.1,68.94 95.1,66.09 70.71,41.71 68.68,41.71 D31.K2 | v225.96,220.52 224.33,222.15 244.65,242.47 245.06,242.47 v262.94,260.35
  Bottom 0.203: v262.94,260.35 264.16,259.13 282.85,259.13 283.67,259.94 A14.E2
TTO_SKIP\  (via drill 0.61)
  Route2 0.203: v228.8,234.34 209.7,215.24 208.89,215.24 197.1,203.45 197.1,201.83 151.59,156.31 151.59,155.5 149.15,153.06 149.15,148.59 139.4,138.84 139.4,135.99 136.14,132.74 136.14,131.93 117.45,113.23 117.45,111.2 117.04,110.79 116.64,110.79 66.24,60.4 66.24,49.84 65.43,49.02 65.43,44.96 D31.J2
  Bottom 0.203: v228.8,234.34 230.84,236.37 262.13,236.37 262.53,236.78 282.45,236.78 283.67,235.56 A14.P2
TXD  (via drill 0.61)
  Top 0.203: v52.83,80.31 52.83,78.28 44.7,70.16 44.7,49.84 43.08,48.21 D33.H2
  Bottom 0.203: v52.83,80.31 53.65,81.13 63.8,81.13 64.62,81.94 C31.V2
VCC  (via drill 0.61)
  Top 0.508: A33.A2 43.48,273.36 47.55,273.36 48.77,274.57 55.27,274.57 55.27,273.76 A32.A2 | A28A.A2 106.48,273.76 106.88,274.17 106.88,282.3 108.1,283.52 156.87,283.52 156.87,273.76 A24.A2 | v145.09,69.34 144.68,68.94 144.68,67.31 D25.A2 | C33.A2 42.67,137.21 41.45,138.43 41.45,201.83 42.27,202.64 B33.A2 | D30.A2 80.47,67.31 80.47,83.97 79.65,84.78 79.65,135.18 80.47,135.99 C30.A2 | v332.44,203.05 332.44,203.45 333.65,204.67 333.65,271.73 334.47,272.54 A10.A2
  Route15 0.508: v115.82,69.34 118.26,66.9 D27.A2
